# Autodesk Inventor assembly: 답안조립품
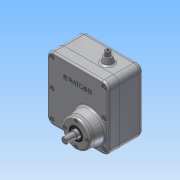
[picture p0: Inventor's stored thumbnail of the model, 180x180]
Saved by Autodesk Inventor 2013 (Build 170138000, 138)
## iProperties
Created: 2015-10
Part Number: 답안조립품
Document SubType Name: Assembly
Designer: Administrator
Author: Administrator
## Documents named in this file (15)
- C:\Users\Administrator\Desktop\351008V1025\답안조립품.iam
- C:\Users\Administrator\Desktop\351008V1025\본체.ipt
- C:\Users\Administrator\Desktop\351008V1025\커버.ipt
- C:\Users\Administrator\Desktop\351008V1025\베어링 6002.ipt
- C:\Users\Administrator\Desktop\351008V1025\베어링 6001.ipt
- C:\Users\Administrator\Desktop\351008V1025\축 커버.ipt
- C:\Users\Administrator\Desktop\351008V1025\M3 x 0.5.ipt
- C:\Users\Administrator\Desktop\351008V1025\오일실 12 x 22.ipt
- C:\Users\Administrator\Desktop\351008V1025\로드 축.ipt
- C:\Users\Administrator\Desktop\351008V1025\로드.ipt
- C:\Users\Administrator\Desktop\351008V1025\편심 축.ipt
- C:\Users\Administrator\Desktop\351008V1025\M4 x 0.7.ipt
- C:\Users\Administrator\Desktop\351008V1025\오일실 15 x 25.ipt
- C:\Users\Administrator\Desktop\351008V1025\슬라이드.ipt
- C:\Users\Administrator\Desktop\351008V1025\가변 스프링.ipt
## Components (11 placed, 3 different names)
1. M4 x 0.7:1
2. M4 x 0.7:2
3. M4 x 0.7:3
4. M4 x 0.7:4
5. M4 x 0.7:5
6. M4 x 0.7:6
7. 가변 스프링:1
8. M3 x 0.5:1
9. M3 x 0.5:2
10. M3 x 0.5:3
11. M3 x 0.5:4
